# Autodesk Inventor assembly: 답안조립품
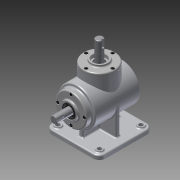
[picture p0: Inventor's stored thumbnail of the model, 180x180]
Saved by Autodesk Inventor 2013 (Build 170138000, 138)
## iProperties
Created: 2015-07
Part Number: 답안조립품
Document SubType Name: Assembly
Designer: Administrator
Author: Administrator
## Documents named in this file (14)
- C:\Users\Administrator\Desktop\450706V1006\답안조립품.iam
- C:\Users\Administrator\Desktop\450706V1006\본체.ipt
- C:\Users\Administrator\Desktop\450706V1006\메인 축.ipt
- 메인 축.ipt
- C:\Users\Administrator\Desktop\450706V1006\베어링 6203.ipt
- C:\Users\Administrator\Desktop\450706V1006\커버.ipt
- C:\Users\Administrator\Desktop\450706V1006\오일실.ipt
- C:\Users\Administrator\Desktop\450706V1006\M4.ipt
- C:\Users\Administrator\Desktop\450706V1006\메인 베벨기어.ipt
- C:\Users\Administrator\Desktop\450706V1006\키 4x4.ipt
- C:\Users\Administrator\Desktop\450706V1006\서브 베벨기어.ipt
- C:\Users\Administrator\Desktop\450706V1006\서브 축.ipt
- 서브 축.ipt
- C:\Users\Administrator\Desktop\450706V1006\키 5x5.ipt
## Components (8 placed, 1 different names)
1. M4:1
2. M4:2
3. M4:3
4. M4:4
5. M4:5
6. M4:6
7. M4:7
8. M4:8
